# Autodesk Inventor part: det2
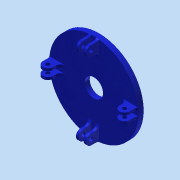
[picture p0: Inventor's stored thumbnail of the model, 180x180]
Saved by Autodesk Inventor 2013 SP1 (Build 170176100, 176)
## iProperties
Created: 2016-04
Part Number: det2
Material: Пластик АБС
Document SubType Name: Modeling
Designer: Кравец
Density: 1 g/cm^3
Author: Кравец
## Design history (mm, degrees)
sketch "Эскиз1"
  geometry: C1 r 3.6 at (0, 0); C2 r 17.5 at (0, 0); 1 further point
  constraints: 2 centre point, 2 coincident
  dimensions: "d0" = 7.2 diameter of C1; "d3" = 35 diameter of C2
extrude "Выдавливание1" new body sketch "Эскиз1" distance "d4" = 2; taper "d5" = 0 deg
sketch "Эскиз2"
  geometry: L1 (-1, 17)-(-2, 17); L2 (-2, 17)-(-2, 13); L3 (-2, 13)-(-1, 13); L4 (-1, 13)-(-1, 17); L5 (1, 17)-(2, 17); L6 (2, 17)-(2, 13); L7 (2, 13)-(1, 13); L8 (1, 13)-(1, 17); C1 r 3.6 at (0, 0) reference; C2 r 17.5 at (0, 0) reference
  constraints: 16 end point, 4 parallel, 2 equal length, 2 horizontal, 2 perpendicular, 1 collinear
  dimensions: "d6" = 2 distance between parallel lines of L8 L4; "d8" = 1 distance of L1.start L1.end; "d9" = 1 distance from line of C1.centre L4 (= 0.5 x d6); "d10" = 0.5 distance edge to line of C2 L1; "d11" = 4 distance of L5.end L6.end
extrude "Выдавливание2" join sketch "Эскиз2" distance "d12" = 5; taper "d13" = 0 deg
fillet "Сопряжение1" dims "d14" = 2
hole "Отверстие1" diameter "d17" = 1.5; stored, may be unused: countersink angle "d21" = 90 deg, drill point angle "d23" = 118 deg; dims "d18" = 6, "d19" = 4, "d20" = 2, "d22" = 8, "d28" = 10, "d29" = 10
fillet "Сопряжение2" dims "d24" = 2
pattern_circular "Круговой массив1" dims "d26" = 360 deg
node "Твердое тело1"
